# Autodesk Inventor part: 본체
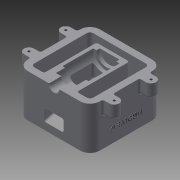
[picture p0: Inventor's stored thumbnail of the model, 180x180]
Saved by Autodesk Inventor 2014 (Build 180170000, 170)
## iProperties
Created: 2018-01
Part Number: 본체
Material: Generic
Document SubType Name: Modeling
Designer: Administrator
Density: 1 g/cm^3
Appearance: Default
Author: Administrator
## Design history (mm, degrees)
sketch "Sketch1"
  geometry: L1 (-40, 55)-(40, 55); L2 (55, 40)-(55, -40); L3 (40, -55)-(-40, -55); L4 (-55, -40)-(-55, 40); L5 (-55, 55)-(55, -55); L6 (55, 55)-(-55, -55); L7 (40, 45)-(-40, 45); L8 (-40, -45)-(40, -45); L9 (45, -40)-(45, 40); L10 (17.238, 25)-(-45, 25); L11 (17.238, 25)-(35, 25); L12 (35, 25)-(35, -25); L13 (35, -25)-(-45, -25); L14 (-45, 40)-(-45, 25); L15 (-45, -25)-(-45, -40); A1 r 15 centre (-40, 40) between (-40, 55) and (-55, 40); A2 r 15 centre (-40, -40) between (-55, -40) and (-40, -55); A3 r 15 centre (40, -40) between (40, -55) and (55, -40); A4 r 15 centre (40, 40) between (55, 40) and (40, 55); A5 r 5 centre (-40, 40) between (-40, 45) and (-45, 40); A6 r 5 centre (-40, -40) between (-45, -40) and (-40, -45); A7 r 5 centre (40, -40) between (40, -45) and (45, -40); A8 r 5 centre (40, 40) between (45, 40) and (40, 45); 1 further point
  constraints: 30 end point, 16 point on circle, 8 centre point, 8 point on line, 8 tangent, 6 perpendicular, 5 parallel, 3 equal radius, 2 midpoint, 1 horizontal, 5 other
  dimensions: "d0" = 110 distance between parallel lines of L2 L4; "d1" = 110 distance between parallel lines of L3 L1; "d2" = 15 radius of A1; "d3" = 10 distance between parallel lines of L2 L9; "d8" = 25 distance from line of L10 point (0, 0); "d9" = 10 distance between parallel lines of L4 L15; "d10" = 45 distance from line of point (0, 0) L15 (derived); "d11" = 25 distance from line of point (0, 0) L13; "d12" = 90 distance between parallel lines of L7 L8; "d13" = 10 distance between parallel lines of L9 L12
extrude "Extrusion1" new body sketch "Sketch1" distance "d14" = 65; taper "d15" = 0 deg
fillet "Fillet1" dims "d25" = 3
sketch "Sketch7"
  geometry: L1 (-55, 0)-(-55, 65) reference; L2 (-55, 65)-(-45, 65) reference; L3 (-45, 65)-(-45, 0) reference; L4 (-45, 0)-(-55, 0) reference; L5 (55, 65)-(55, 0) reference; L6 (55, 0)-(-35, 0) reference; L7 (-35, 0)-(-35, 65) reference; L8 (-35, 65)-(55, 65) reference; L9 (55, 65)-(-35, 65); L10 (55, 65)-(55, 72.5); L11 (55, 72.5)-(36, 72.5); L12 (36, 72.5)-(36, 80); L13 (35, 81)-(22, 81); L14 (22, 81)-(22, 84); L15 (21, 85)-(-24, 85); L16 (-25, 84)-(-25, 80); L17 (-25, 80)-(-29, 80); L18 (-30, 79)-(-30, 65); A1 r 1 centre (35, 80) between (36, 80) and (35, 81); A2 r 1 centre (21, 84) between (22, 84) and (21, 85); A3 r 1 centre (-24, 84) between (-24, 85) and (-25, 84); A4 r 1 centre (-29, 79) between (-29, 80) and (-30, 79); 5 further points
  constraints: 20 end point, 10 point on line, 9 perpendicular, 8 point on circle, 8 tangent, 4 centre point, 3 equal radius, 1 collinear
  dimensions: "d40" = 15 diameter of L10.end L8; "d41" = 19 distance from line of L11.end L10; "d42" = 32 diameter of point (36, 81) L8; "d43" = 14 distance from line of L13.end L12; "d44" = 40 diameter of L15 L8; "d45" = 47 distance from line of point (-25, 85) L14; "d46" = 5 distance from line of point (-30, 80) L16; "d47" = 30 diameter of L17 L9; "d76" = 1 radius of A1
revolve "Revolution1" sketch "Sketch7" stored, may be unused: angle "d48" = 90 deg
sketch "Sketch11"
  geometry: L1 (-30, 65)-(-30, 51) reference; L2 (-29, 50)-(-25, 50) reference; L3 (-25, 50)-(-25, 46) reference; L4 (22, 46)-(22, 49) reference; L5 (22, 49)-(35, 49) reference; L6 (36, 50)-(36, 57.5) reference; L7 (36, 57.5)-(55, 57.5) reference; L8 (55, 57.5)-(55, 0) reference; L9 (55, 0)-(-35, 0) reference; L10 (-35, 0)-(-35, 65) reference; L11 (-35, 65)-(-30, 65) reference; L12 (-55, 65)-(-45, 65) reference; L13 (-45, 65)-(-45, 0) reference; L14 (-45, 0)-(-55, 0) reference; L15 (-55, 0)-(-55, 65) reference; L16 (-35, 30)-(45, 8.564); L17 (45, 0)-(45, 8.564); L18 (-35, 0)-(45, 0); L19 (-35, 30)-(-35, 0); L20 (-24, 45)-(21, 45) reference; A1 r 1 centre (-29, 51) between (-30, 51) and (-29, 50) reference; A2 r 1 centre (-24, 46) between (-25, 46) and (-24, 45) reference; A3 r 1 centre (21, 46) between (21, 45) and (22, 46) reference; A4 r 1 centre (35, 50) between (35, 49) and (36, 50) reference; 1 further point
  constraints: 8 end point, 3 point on line, 2 collinear
  dimensions: "d61" = 30 distance from line of L16.start L14; "d63" = 105 deg angle of L10 L16; "d64" = 8.56406 distance from line of L16.end L9; "d65" = 80 distance from line of L17.start L10
extrude "Extrusion3" cut sketch "Sketch11" stored distance "d66" = 55; taper "d67" = 0 deg
sketch "Sketch12"
  geometry: L1 (-35, 30)-(42, 9.368) reference; L2 (-17.776, 30.561)-(55, 11.061); L3 (55, 0)-(55, 65) reference; L4 (-24, 45)-(21, 45) reference; L5 (19.224, 38.647)-(55, 29.061); L6 (17, 45)-(17, 41.545); L7 (-20, 45)-(-20, 33.459); L8 (55, 29.061)-(55, 11.061); L9 (-20, 45)-(-20, 62.933); L10 (-20, 62.933)-(17, 62.933); L11 (17, 62.933)-(17, 45); A1 r 3 centre (20, 41.545) between (17, 41.545) and (19.224, 38.647); A2 r 3 centre (-17, 33.459) between (-20, 33.459) and (-17.776, 30.561); 6 further points; 2 other entities
  constraints: 16 end point, 5 parallel, 4 point on circle, 4 point on line, 4 tangent, 2 centre point, 2 perpendicular, 1 equal radius, 1 midpoint, 2 other
  dimensions: "d68" = 5 distance between parallel lines of L2 L1; "d70" = 18 distance of L5.end L2.end; "d71" = 18.5 distance of L7.start point (-1.5, 45); "d72" = 18.5 distance of point (-1.5, 45) L6.start; "d73" = 3 radius of A1; "d78" = 17.93347 distance between parallel lines of L10 L4
extrude "Extrusion5" cut sketch "Sketch12" stored distance "d79" = 30; taper "d80" = 0 deg
fillet "Fillet2" dims "d81" = 3
chamfer "Chamfer1" distance "d82" = 1; stored, may be unused: second distance "d83" = 2, angle "d84" = 45 deg
sketch "Sketch13"
  geometry: A1 r 10 centre (-28, -65) between (-38, -65) and (-18, -65) reference; A2 r 10 centre (28, -65) between (18, -65) and (38, -65) reference; A3 r 10 centre (28, 65) between (38, 65) and (18, 65) reference; A4 r 10 centre (-28, 65) between (-18, 65) and (-38, 65) reference; 5 further points
  constraints: 4 coincident
hole "Hole1" sketch "Sketch13" at (-28, 65), (28, 65), (28, -65), (-28, -65) diameter "d85" = 3.459; stored, may be unused: countersink angle "d89" = 90 deg, drill point angle "d91" = 118 deg; dims "d86" = 9, "d87" = 4, "d88" = 2, "d90" = 11
fillet "Fillet24" dims "d113" = 3
fillet "Fillet25" dims "d114" = 3
sketch "Sketch14"
  geometry: L1 (-40, -55)-(40, -55) reference; L2 (55, -40)-(55, 40) reference; L3 (40, 55)-(-40, 55) reference; L4 (-55, 40)-(-55, 8.5) reference; L5 (-35.5, 65)-(-35.5, 55); L6 (-20.5, 65)-(-20.5, 55); L7 (-35.5, 55)-(-20.5, 55); L8 (-55, 0)-(55, 0); L9 (0, 55)-(0, -55); L10 (-40, 55)-(40, 55); L11 (35.5, 55)-(20.5, 55); L12 (35.5, 65)-(35.5, 55); L13 (20.5, 65)-(20.5, 55); L14 (45, -40)-(45, 40); L15 (0, -55)-(0, 55); L16 (-40, -45)-(40, -45); L17 (-45, -28)-(-45, -40); L18 (55, 40)-(55, -40); L19 (-40, -55)-(40, -55); L20 (40, -55)-(-40, -55); L21 (-20.5, -65)-(-20.5, -55); L22 (-35.5, -55)-(-20.5, -55); L23 (-55, -40)-(-55, -8.5); L24 (-35.5, -65)-(-35.5, -55); L25 (20.5, -65)-(20.5, -55); L26 (35.5, -55)-(20.5, -55); L27 (35.5, -65)-(35.5, -55); A1 r 5 centre (-40, 40) between (-40, 45) and (-45, 40) reference; A2 r 5 centre (40, 40) between (45, 40) and (40, 45) reference; A3 r 15 centre (40, 40) between (55, 40) and (40, 55) reference; A4 r 15 centre (-40, 40) between (-40, 55) and (-55, 40) reference; A5 r 7.5 centre (-28, 65) between (-20.5, 65) and (-35.5, 65); A6 r 15 centre (40, 40) between (55, 40) and (40, 55); A7 r 7.5 centre (28, 65) between (35.5, 65) and (20.5, 65); A8 r 5 centre (40, -40) between (40, -45) and (45, -40); A9 r 5 centre (-40, -40) between (-45, -40) and (-40, -45); A10 r 15 centre (-40, -40) between (-55, -40) and (-40, -55); A11 r 7.5 centre (-28, -65) between (-35.5, -65) and (-20.5, -65); A12 r 15 centre (40, -40) between (40, -55) and (55, -40); A13 r 15 centre (40, -40) between (40, -55) and (55, -40); A14 r 7.5 centre (28, -65) between (20.5, -65) and (35.5, -65); 2 further points
  constraints: 46 end point, 33 symmetric about line, 20 point on circle, 10 centre point, 8 point on line, 3 midpoint, 2 parallel, 2 tangent, 1 perpendicular, 9 other
  dimensions: "d116" = 15 diameter of A5; "d117" = 27 distance from line of L4 A5.centre; "d118" = 10 distance from line of A5.centre L3
extrude "Extrusion6" join sketch "Sketch14" distance "d119" = 20; taper "d120" = 0 deg
sketch "Sketch15"
  geometry: A1 r 7.5 centre (-28, -65) between (-35.5, -65) and (-20.5, -65) reference; A2 r 7.5 centre (28, -65) between (20.5, -65) and (35.5, -65) reference; A3 r 7.5 centre (28, 65) between (35.5, 65) and (20.5, 65) reference; A4 r 7.5 centre (-28, 65) between (-20.5, 65) and (-35.5, 65) reference; 5 further points
  constraints: 4 coincident
hole "Hole2" sketch "Sketch15" at (-28, 65), (28, 65), (28, -65), (-28, -65) diameter "d121" = 3.459; stored, may be unused: countersink angle "d125" = 90 deg, drill point angle "d127" = 118 deg; dims "d122" = 9, "d123" = 4, "d124" = 2, "d126" = 11
workplane "Work Plane2"
sketch "Sketch17"
  geometry: L1 (95, 0)-(95, 65) reference; L2 (95, 0)-(80, 0) reference; 2 further points
  constraints: 1 other
  dimensions: "d129" = 55 distance from line of L1 point (40, 20); "d130" = 20 distance from line of L2 point (40, 20)
emboss "Emboss2" sketch "Sketch17" dims "d0" = 110, "d1" = 110, "d2" = 15, "d3" = 10, "d8" = 25, "d9" = 10, "d10" = 45 (derived), "d11" = 25, "d12" = 90, "d13" = 10, "d131" = 0.5, "d132" = 0
fillet "Fillet26" dims "d133" = 3
fillet "Fillet27" dims "d134" = 3
fillet "Fillet28" dims "d135" = 3
fillet "Fillet29" dims "d136" = 3
fillet "Fillet30" dims "d137" = 3
fillet "Fillet31" dims "d138" = 3
fillet "Fillet32" dims "d139" = 3
fillet "Fillet33" dims "d140" = 3
fillet "Fillet34" dims "d141" = 3
body "Solid1"
node "Project Cut Edges4"
node "Project Cut Edges8"
